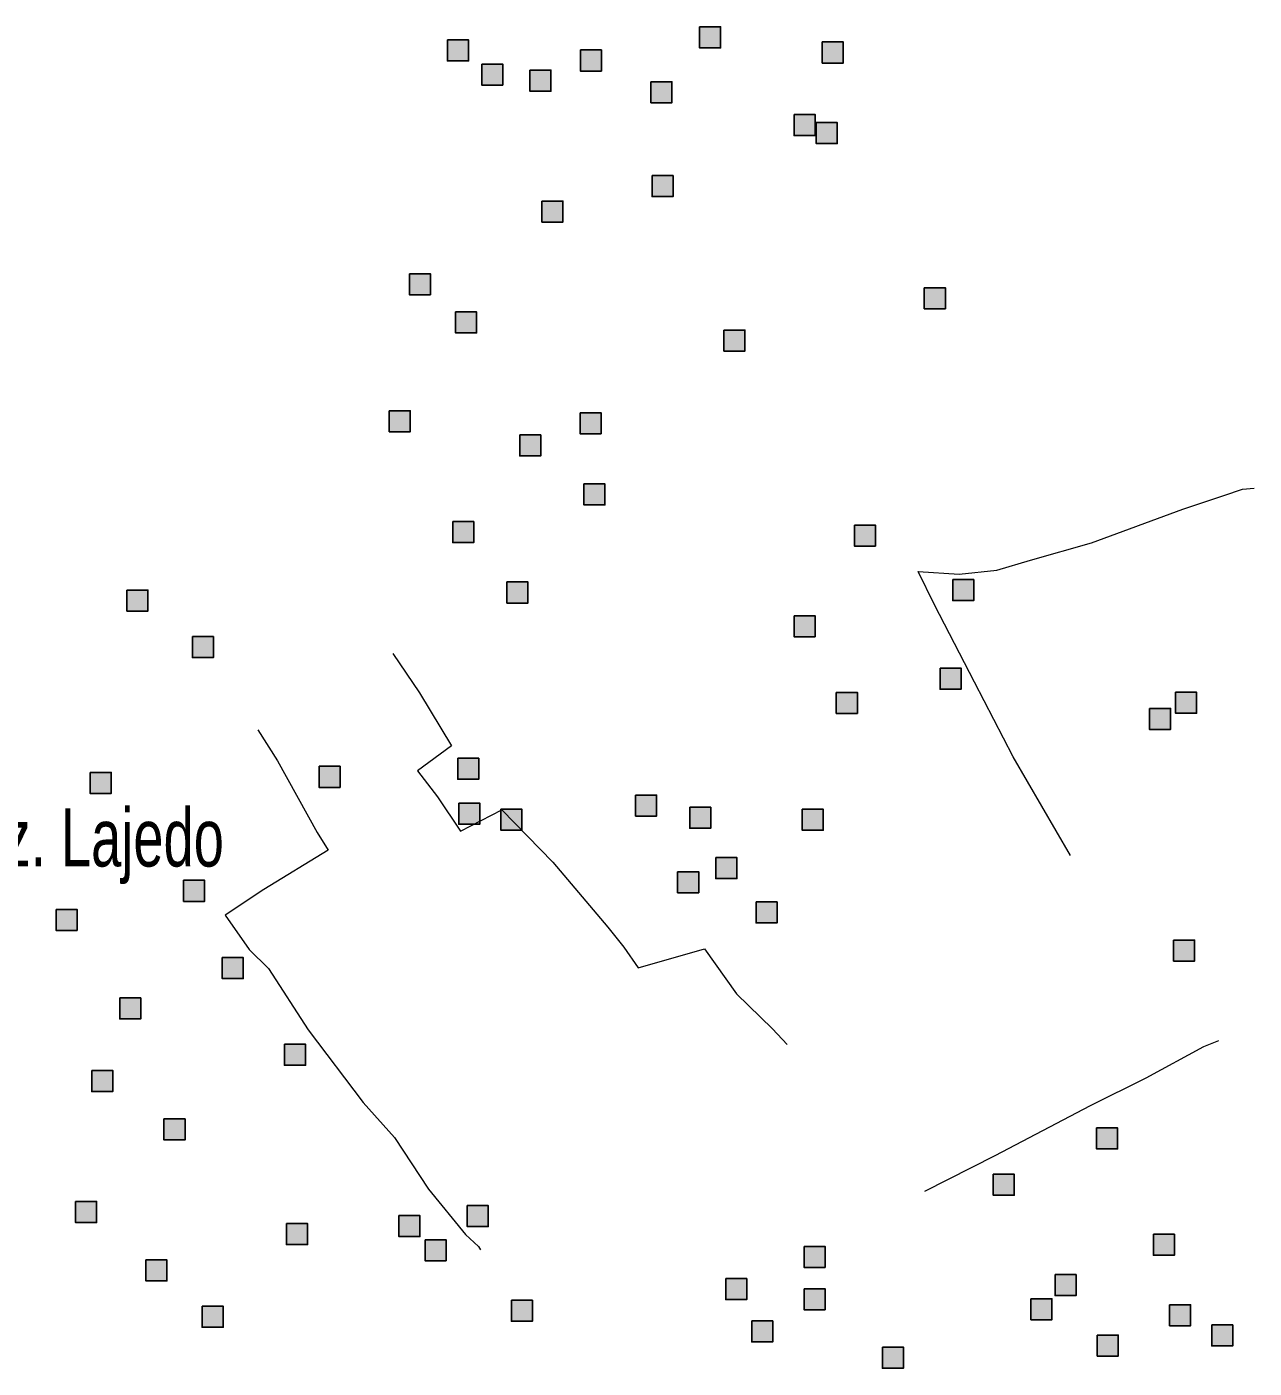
# Model space of a CAD drawing. Extents: x 445.6 to 500, y 8618.1 to 8673.4.
# Drawn here: x 476.597 to 479.984, y 8626.244 to 8629.943 of the extents above; entities that cross this region are included whole.
import ezdxf
from ezdxf.enums import TextEntityAlignment as Align

# ---------------------------------------------------------------- set-up
doc = ezdxf.new("R2010")
doc.units = 0
doc.header["$LTSCALE"] = 0.064
doc.linetypes.add('DOT_DASHED', pattern=[7.7, 5, -1.2, 0.3, -1.2])
doc.layers.add('2', color=7, linetype='Continuous', lineweight=25)
doc.layers.add('22', color=7, linetype='DOT_DASHED', lineweight=13)
doc.layers.add('61', color=7, linetype='Continuous')

msp = doc.modelspace()

# ---------------------------------------------------------------- hatches: boundary and pattern name
at = {"layer": '2'}
for points in [[(478.4532, 8629.9434), (478.5112, 8629.9434), (478.5112, 8629.8854), (478.4532, 8629.8854)], [(477.7578, 8629.9072), (477.8158, 8629.9072), (477.8158, 8629.8492), (477.7578, 8629.8492)], [(478.1246, 8629.8795), (478.1826, 8629.8795), (478.1826, 8629.8215), (478.1246, 8629.8215)], [(478.7919, 8629.9016), (478.8499, 8629.9016), (478.8499, 8629.8436), (478.7919, 8629.8436)], [(477.8521, 8629.8405), (477.9101, 8629.8405), (477.9101, 8629.7825), (477.8521, 8629.7825)], [(477.9851, 8629.8239), (478.0431, 8629.8239), (478.0431, 8629.7659), (477.9851, 8629.7659)], [(478.3191, 8629.792), (478.3771, 8629.792), (478.3771, 8629.734), (478.3191, 8629.734)], [(478.7143, 8629.7016), (478.7723, 8629.7016), (478.7723, 8629.6436), (478.7143, 8629.6436)], [(478.7753, 8629.6793), (478.8333, 8629.6793), (478.8333, 8629.6213), (478.7753, 8629.6213)], [(478.3224, 8629.5331), (478.3804, 8629.5331), (478.3804, 8629.4751), (478.3224, 8629.4751)], [(478.0183, 8629.4626), (478.0763, 8629.4626), (478.0763, 8629.4046), (478.0183, 8629.4046)], [(477.6526, 8629.2625), (477.7106, 8629.2625), (477.7106, 8629.2045), (477.6526, 8629.2045)], [(479.0735, 8629.2236), (479.1315, 8629.2236), (479.1315, 8629.1656), (479.0735, 8629.1656)], [(477.78, 8629.1569), (477.838, 8629.1569), (477.838, 8629.0989), (477.78, 8629.0989)], [(478.5204, 8629.1068), (478.5784, 8629.1068), (478.5784, 8629.0488), (478.5204, 8629.0488)], [(477.5971, 8628.8845), (477.6551, 8628.8845), (477.6551, 8628.8265), (477.5971, 8628.8265)], [(478.1236, 8628.879), (478.1816, 8628.879), (478.1816, 8628.821), (478.1236, 8628.821)], [(477.9573, 8628.8178), (478.0153, 8628.8178), (478.0153, 8628.7598), (477.9573, 8628.7598)], [(478.1342, 8628.6826), (478.1922, 8628.6826), (478.1922, 8628.6246), (478.1342, 8628.6246)], [(477.7722, 8628.5788), (477.8302, 8628.5788), (477.8302, 8628.5208), (477.7722, 8628.5208)], [(478.8806, 8628.569), (478.9386, 8628.569), (478.9386, 8628.511), (478.8806, 8628.511)], [(476.8731, 8628.3898), (476.9311, 8628.3898), (476.9311, 8628.3318), (476.8731, 8628.3318)], [(477.9219, 8628.4121), (477.9799, 8628.4121), (477.9799, 8628.3541), (477.9219, 8628.3541)], [(479.1521, 8628.4189), (479.2101, 8628.4189), (479.2101, 8628.3609), (479.1521, 8628.3609)], [(478.7143, 8628.3189), (478.7723, 8628.3189), (478.7723, 8628.2609), (478.7143, 8628.2609)], [(477.054, 8628.2617), (477.112, 8628.2617), (477.112, 8628.2037), (477.054, 8628.2037)], [(479.1171, 8628.1744), (479.1751, 8628.1744), (479.1751, 8628.1164), (479.1171, 8628.1164)], [(478.8307, 8628.1077), (478.8887, 8628.1077), (478.8887, 8628.0497), (478.8307, 8628.0497)], [(479.7668, 8628.1079), (479.8248, 8628.1079), (479.8248, 8628.0499), (479.7668, 8628.0499)], [(479.6948, 8628.0635), (479.7528, 8628.0635), (479.7528, 8628.0055), (479.6948, 8628.0055)], [(477.7859, 8627.9259), (477.8439, 8627.9259), (477.8439, 8627.8679), (477.7859, 8627.8679)], [(476.7718, 8627.887), (476.8298, 8627.887), (476.8298, 8627.829), (476.7718, 8627.829)], [(477.4035, 8627.9036), (477.4615, 8627.9036), (477.4615, 8627.8456), (477.4035, 8627.8456)], [(477.7889, 8627.802), (477.8469, 8627.802), (477.8469, 8627.744), (477.7889, 8627.744)], [(478.2766, 8627.8242), (478.3346, 8627.8242), (478.3346, 8627.7662), (478.2766, 8627.7662)], [(477.9053, 8627.7853), (477.9633, 8627.7853), (477.9633, 8627.7273), (477.9053, 8627.7273)], [(478.4262, 8627.7909), (478.4842, 8627.7909), (478.4842, 8627.7329), (478.4262, 8627.7329)], [(478.7365, 8627.7853), (478.7945, 8627.7853), (478.7945, 8627.7273), (478.7365, 8627.7273)], [(478.4982, 8627.6519), (478.5562, 8627.6519), (478.5562, 8627.5939), (478.4982, 8627.5939)], [(478.3929, 8627.613), (478.4509, 8627.613), (478.4509, 8627.555), (478.3929, 8627.555)], [(477.0294, 8627.5892), (477.0874, 8627.5892), (477.0874, 8627.5312), (477.0294, 8627.5312)], [(476.6776, 8627.509), (476.7356, 8627.509), (476.7356, 8627.451), (476.6776, 8627.451)], [(478.6091, 8627.5296), (478.6671, 8627.5296), (478.6671, 8627.4716), (478.6091, 8627.4716)], [(479.7613, 8627.4243), (479.8193, 8627.4243), (479.8193, 8627.3663), (479.7613, 8627.3663)], [(477.1362, 8627.3759), (477.1942, 8627.3759), (477.1942, 8627.3179), (477.1362, 8627.3179)], [(476.8535, 8627.2647), (476.9115, 8627.2647), (476.9115, 8627.2067), (476.8535, 8627.2067)], [(477.308, 8627.1369), (477.366, 8627.1369), (477.366, 8627.0789), (477.308, 8627.0789)], [(476.776, 8627.0646), (476.834, 8627.0646), (476.834, 8627.0066), (476.776, 8627.0066)], [(476.9755, 8626.9312), (477.0335, 8626.9312), (477.0335, 8626.8732), (476.9755, 8626.8732)], [(479.5488, 8626.9064), (479.6068, 8626.9064), (479.6068, 8626.8484), (479.5488, 8626.8484)], [(479.2638, 8626.7786), (479.3218, 8626.7786), (479.3218, 8626.7206), (479.2638, 8626.7206)], [(476.7316, 8626.7033), (476.7896, 8626.7033), (476.7896, 8626.6453), (476.7316, 8626.6453)], [(477.8123, 8626.6922), (477.8703, 8626.6922), (477.8703, 8626.6342), (477.8123, 8626.6342)], [(477.6238, 8626.6644), (477.6818, 8626.6644), (477.6818, 8626.6064), (477.6238, 8626.6064)], [(477.3135, 8626.6422), (477.3715, 8626.6422), (477.3715, 8626.5842), (477.3135, 8626.5842)], [(477.6959, 8626.5977), (477.7539, 8626.5977), (477.7539, 8626.5397), (477.6959, 8626.5397)], [(478.7416, 8626.5795), (478.7996, 8626.5795), (478.7996, 8626.5215), (478.7416, 8626.5215)], [(479.7058, 8626.6128), (479.7638, 8626.6128), (479.7638, 8626.5548), (479.7058, 8626.5548)], [(476.9256, 8626.5421), (476.9836, 8626.5421), (476.9836, 8626.4841), (476.9256, 8626.4841)], [(478.5255, 8626.4905), (478.5835, 8626.4905), (478.5835, 8626.4325), (478.5255, 8626.4325)], [(479.4343, 8626.5016), (479.4923, 8626.5016), (479.4923, 8626.4436), (479.4343, 8626.4436)], [(477.9342, 8626.431), (477.9922, 8626.431), (477.9922, 8626.373), (477.9342, 8626.373)], [(478.7416, 8626.4627), (478.7996, 8626.4627), (478.7996, 8626.4047), (478.7416, 8626.4047)], [(479.3678, 8626.4349), (479.4258, 8626.4349), (479.4258, 8626.3769), (479.3678, 8626.3769)], [(477.0808, 8626.4143), (477.1388, 8626.4143), (477.1388, 8626.3563), (477.0808, 8626.3563)], [(479.7502, 8626.4183), (479.8082, 8626.4183), (479.8082, 8626.3603), (479.7502, 8626.3603)], [(478.5975, 8626.3738), (478.6555, 8626.3738), (478.6555, 8626.3158), (478.5975, 8626.3158)], [(479.8665, 8626.3627), (479.9245, 8626.3627), (479.9245, 8626.3047), (479.8665, 8626.3047)], [(479.5507, 8626.3349), (479.6087, 8626.3349), (479.6087, 8626.2769), (479.5507, 8626.2769)], [(478.9577, 8626.3015), (479.0157, 8626.3015), (479.0157, 8626.2435), (478.9577, 8626.2435)]]:
    msp.add_hatch(color=256, dxfattribs=at).paths.add_polyline_path(points)

# ---------------------------------------------------------------- linework, layer by layer
for points in [[(478.4532, 8629.9434), (478.5112, 8629.9434), (478.5112, 8629.8854), (478.4532, 8629.8854)], [(477.7578, 8629.9072), (477.8158, 8629.9072), (477.8158, 8629.8492), (477.7578, 8629.8492)], [(478.1246, 8629.8795), (478.1826, 8629.8795), (478.1826, 8629.8215), (478.1246, 8629.8215)], [(478.7919, 8629.9016), (478.8499, 8629.9016), (478.8499, 8629.8436), (478.7919, 8629.8436)], [(477.8521, 8629.8405), (477.9101, 8629.8405), (477.9101, 8629.7825), (477.8521, 8629.7825)], [(477.9851, 8629.8239), (478.0431, 8629.8239), (478.0431, 8629.7659), (477.9851, 8629.7659)], [(478.3191, 8629.792), (478.3771, 8629.792), (478.3771, 8629.734), (478.3191, 8629.734)], [(478.7143, 8629.7016), (478.7723, 8629.7016), (478.7723, 8629.6436), (478.7143, 8629.6436)], [(478.7753, 8629.6793), (478.8333, 8629.6793), (478.8333, 8629.6213), (478.7753, 8629.6213)], [(478.3224, 8629.5331), (478.3804, 8629.5331), (478.3804, 8629.4751), (478.3224, 8629.4751)], [(478.0183, 8629.4626), (478.0763, 8629.4626), (478.0763, 8629.4046), (478.0183, 8629.4046)], [(477.6526, 8629.2625), (477.7106, 8629.2625), (477.7106, 8629.2045), (477.6526, 8629.2045)], [(479.0735, 8629.2236), (479.1315, 8629.2236), (479.1315, 8629.1656), (479.0735, 8629.1656)], [(477.78, 8629.1569), (477.838, 8629.1569), (477.838, 8629.0989), (477.78, 8629.0989)], [(478.5204, 8629.1068), (478.5784, 8629.1068), (478.5784, 8629.0488), (478.5204, 8629.0488)], [(477.5971, 8628.8845), (477.6551, 8628.8845), (477.6551, 8628.8265), (477.5971, 8628.8265)], [(478.1236, 8628.879), (478.1816, 8628.879), (478.1816, 8628.821), (478.1236, 8628.821)], [(477.9573, 8628.8178), (478.0153, 8628.8178), (478.0153, 8628.7598), (477.9573, 8628.7598)], [(478.1342, 8628.6826), (478.1922, 8628.6826), (478.1922, 8628.6246), (478.1342, 8628.6246)], [(477.7722, 8628.5788), (477.8302, 8628.5788), (477.8302, 8628.5208), (477.7722, 8628.5208)], [(478.8806, 8628.569), (478.9386, 8628.569), (478.9386, 8628.511), (478.8806, 8628.511)], [(476.8731, 8628.3898), (476.9311, 8628.3898), (476.9311, 8628.3318), (476.8731, 8628.3318)], [(477.9219, 8628.4121), (477.9799, 8628.4121), (477.9799, 8628.3541), (477.9219, 8628.3541)], [(479.1521, 8628.4189), (479.2101, 8628.4189), (479.2101, 8628.3609), (479.1521, 8628.3609)], [(478.7143, 8628.3189), (478.7723, 8628.3189), (478.7723, 8628.2609), (478.7143, 8628.2609)], [(477.054, 8628.2617), (477.112, 8628.2617), (477.112, 8628.2037), (477.054, 8628.2037)], [(479.1171, 8628.1744), (479.1751, 8628.1744), (479.1751, 8628.1164), (479.1171, 8628.1164)], [(478.8307, 8628.1077), (478.8887, 8628.1077), (478.8887, 8628.0497), (478.8307, 8628.0497)], [(479.7668, 8628.1079), (479.8248, 8628.1079), (479.8248, 8628.0499), (479.7668, 8628.0499)], [(479.6948, 8628.0635), (479.7528, 8628.0635), (479.7528, 8628.0055), (479.6948, 8628.0055)], [(477.7859, 8627.9259), (477.8439, 8627.9259), (477.8439, 8627.8679), (477.7859, 8627.8679)], [(476.7718, 8627.887), (476.8298, 8627.887), (476.8298, 8627.829), (476.7718, 8627.829)], [(477.4035, 8627.9036), (477.4615, 8627.9036), (477.4615, 8627.8456), (477.4035, 8627.8456)], [(477.7889, 8627.802), (477.8469, 8627.802), (477.8469, 8627.744), (477.7889, 8627.744)], [(478.2766, 8627.8242), (478.3346, 8627.8242), (478.3346, 8627.7662), (478.2766, 8627.7662)], [(477.9053, 8627.7853), (477.9633, 8627.7853), (477.9633, 8627.7273), (477.9053, 8627.7273)], [(478.4262, 8627.7909), (478.4842, 8627.7909), (478.4842, 8627.7329), (478.4262, 8627.7329)], [(478.7365, 8627.7853), (478.7945, 8627.7853), (478.7945, 8627.7273), (478.7365, 8627.7273)], [(478.4982, 8627.6519), (478.5562, 8627.6519), (478.5562, 8627.5939), (478.4982, 8627.5939)], [(478.3929, 8627.613), (478.4509, 8627.613), (478.4509, 8627.555), (478.3929, 8627.555)], [(477.0294, 8627.5892), (477.0874, 8627.5892), (477.0874, 8627.5312), (477.0294, 8627.5312)], [(476.6776, 8627.509), (476.7356, 8627.509), (476.7356, 8627.451), (476.6776, 8627.451)], [(478.6091, 8627.5296), (478.6671, 8627.5296), (478.6671, 8627.4716), (478.6091, 8627.4716)], [(479.7613, 8627.4243), (479.8193, 8627.4243), (479.8193, 8627.3663), (479.7613, 8627.3663)], [(477.1362, 8627.3759), (477.1942, 8627.3759), (477.1942, 8627.3179), (477.1362, 8627.3179)], [(476.8535, 8627.2647), (476.9115, 8627.2647), (476.9115, 8627.2067), (476.8535, 8627.2067)], [(477.308, 8627.1369), (477.366, 8627.1369), (477.366, 8627.0789), (477.308, 8627.0789)], [(476.776, 8627.0646), (476.834, 8627.0646), (476.834, 8627.0066), (476.776, 8627.0066)], [(476.9755, 8626.9312), (477.0335, 8626.9312), (477.0335, 8626.8732), (476.9755, 8626.8732)], [(479.5488, 8626.9064), (479.6068, 8626.9064), (479.6068, 8626.8484), (479.5488, 8626.8484)], [(479.2638, 8626.7786), (479.3218, 8626.7786), (479.3218, 8626.7206), (479.2638, 8626.7206)], [(476.7316, 8626.7033), (476.7896, 8626.7033), (476.7896, 8626.6453), (476.7316, 8626.6453)], [(477.8123, 8626.6922), (477.8703, 8626.6922), (477.8703, 8626.6342), (477.8123, 8626.6342)], [(477.6238, 8626.6644), (477.6818, 8626.6644), (477.6818, 8626.6064), (477.6238, 8626.6064)], [(477.3135, 8626.6422), (477.3715, 8626.6422), (477.3715, 8626.5842), (477.3135, 8626.5842)], [(477.6959, 8626.5977), (477.7539, 8626.5977), (477.7539, 8626.5397), (477.6959, 8626.5397)], [(478.7416, 8626.5795), (478.7996, 8626.5795), (478.7996, 8626.5215), (478.7416, 8626.5215)], [(479.7058, 8626.6128), (479.7638, 8626.6128), (479.7638, 8626.5548), (479.7058, 8626.5548)], [(476.9256, 8626.5421), (476.9836, 8626.5421), (476.9836, 8626.4841), (476.9256, 8626.4841)], [(478.5255, 8626.4905), (478.5835, 8626.4905), (478.5835, 8626.4325), (478.5255, 8626.4325)], [(479.4343, 8626.5016), (479.4923, 8626.5016), (479.4923, 8626.4436), (479.4343, 8626.4436)], [(477.9342, 8626.431), (477.9922, 8626.431), (477.9922, 8626.373), (477.9342, 8626.373)], [(478.7416, 8626.4627), (478.7996, 8626.4627), (478.7996, 8626.4047), (478.7416, 8626.4047)], [(479.3678, 8626.4349), (479.4258, 8626.4349), (479.4258, 8626.3769), (479.3678, 8626.3769)], [(477.0808, 8626.4143), (477.1388, 8626.4143), (477.1388, 8626.3563), (477.0808, 8626.3563)], [(479.7502, 8626.4183), (479.8082, 8626.4183), (479.8082, 8626.3603), (479.7502, 8626.3603)], [(478.5975, 8626.3738), (478.6555, 8626.3738), (478.6555, 8626.3158), (478.5975, 8626.3158)], [(479.8665, 8626.3627), (479.9245, 8626.3627), (479.9245, 8626.3047), (479.8665, 8626.3047)], [(479.5507, 8626.3349), (479.6087, 8626.3349), (479.6087, 8626.2769), (479.5507, 8626.2769)], [(478.9577, 8626.3015), (479.0157, 8626.3015), (479.0157, 8626.2435), (478.9577, 8626.2435)]]:
    msp.add_lwpolyline(points, close=True, dxfattribs=at)
at = {"layer": '22'}
for points in [[(479.4771, 8627.6577), (479.3184, 8627.9299), (479.2116, 8628.1362), (479.1014, 8628.3494), (479.0565, 8628.441), (479.1701, 8628.4341), (479.2734, 8628.4444), (479.3664, 8628.4719), (479.5352, 8628.5201), (479.7866, 8628.6129), (479.9002, 8628.6507), (479.9519, 8628.6679), (479.9837, 8628.6713)], [(477.6071, 8628.2148), (477.6807, 8628.1062), (477.7692, 8627.9599), (477.6752, 8627.8909), (477.7305, 8627.8191), (477.7941, 8627.7252), (477.9075, 8627.7832), (478.0485, 8627.6396), (478.2005, 8627.4602), (478.2448, 8627.4049), (478.2841, 8627.348), (478.4665, 8627.4005), (478.555, 8627.2762), (478.6546, 8627.1796), (478.6946, 8627.1362)], [(477.2344, 8628.0046), (477.2889, 8627.9186), (477.3981, 8627.7208), (477.4286, 8627.6727), (477.2508, 8627.5636), (477.1442, 8627.4926), (477.2102, 8627.3988), (477.2635, 8627.3455), (477.3729, 8627.1764), (477.5253, 8626.9761), (477.6116, 8626.8797), (477.7056, 8626.7377), (477.8079, 8626.6121), (477.8434, 8626.5791), (477.8486, 8626.5703)], [(479.0745, 8626.7316), (479.2689, 8626.8304), (479.5325, 8626.9682), (479.6858, 8627.0447), (479.8451, 8627.1304), (479.8863, 8627.1476)]]:
    msp.add_lwpolyline(points, dxfattribs=at)

# ---------------------------------------------------------------- texts
at = {"layer": '61', "width": 0.7}
msp.add_text('Faz. Lajedo', height=0.16, dxfattribs=at).set_placement((476.7495, 8627.6273), align=Align.CENTER)

doc.saveas('drawing.dxf')
